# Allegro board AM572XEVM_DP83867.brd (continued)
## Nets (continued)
VOUT1_D12: P18.20 R136.2
VOUT1_D13: P18.15 R138.2
VOUT1_D14: P18.17 R139.2
VOUT1_D15: P18.14 R140.2
VOUT1_D16: P18.50 R141.2
VOUT1_D17: P18.51 R142.2
VOUT1_D18: P18.21 R143.2
VOUT1_D19: P18.22 R144.2
VOUT1_D20: P18.19 R145.2
VOUT1_D21: P18.23 R146.2
VOUT1_D22: P18.52 R147.2
VOUT1_D23: P18.24 R148.2
VOUT1_DE: P18.53 R150.2
VOUT1_HSYNC: P18.27 R152.2
VOUT1_RD0: R124.1 U11.F11(VOUT1_D0)
VOUT1_RD1: R125.1 U11.G10(VOUT1_D1)
VOUT1_RD2: R126.1 U11.F10(VOUT1_D2)
VOUT1_RD3: R127.1 U11.G11(VOUT1_D3)
VOUT1_RD4: R128.1 U11.E9(VOUT1_D4)
VOUT1_RD5: R129.1 U11.F9(VOUT1_D5)
VOUT1_RD6: R130.1 U11.F8(VOUT1_D6)
VOUT1_RD7: R131.1 U11.E7(VOUT1_D7)
VOUT1_RD8: R132.1 U11.E8(VOUT1_D8)
VOUT1_RD9: R133.1 U11.D9(VOUT1_D9)
VOUT1_RD10: R134.1 U11.D7(VOUT1_D10)
VOUT1_RD11: R135.1 U11.D8(VOUT1_D11)
VOUT1_RD12: R136.1 U11.A5(VOUT1_D12)
VOUT1_RD13: R138.1 U11.C6(VOUT1_D13)
VOUT1_RD14: R139.1 U11.C8(VOUT1_D14)
VOUT1_RD15: R140.1 U11.C7(VOUT1_D15)
VOUT1_RD16: R141.1 U11.B7(VOUT1_D16)
VOUT1_RD17: R142.1 U11.B8(VOUT1_D17)
VOUT1_RD18: R143.1 U11.A7(VOUT1_D18)
VOUT1_RD19: R144.1 U11.A8(VOUT1_D19)
VOUT1_RD20: R145.1 U11.C9(VOUT1_D20)
VOUT1_RD21: R146.1 U11.A9(VOUT1_D21)
VOUT1_RD22: R147.1 U11.B9(VOUT1_D22)
VOUT1_RD23: R148.1 U11.A10(VOUT1_D23)
VOUT1_RDCLK: R149.1 U11.D11(VOUT1_CLK)
VOUT1_RDE: R150.1 U11.B10(VOUT1_DE)
VOUT1_RHSYNC: R152.1 U11.C11(VOUT1_HSYNC)
VOUT1_RVSYNC: R153.1 U11.E11(VOUT1_VSYNC)
VOUT1_VSYNC: P18.28 R153.2
VTT: C296.1 C297.1 C298.1 C299.1 C313.1 C314.1 C328.1 C329.1 C330.1 C331.1 C332.1 C333.1 C342.1 C343.1 C351.1 C352.1 C353.1 C358.1 C362.1 C370.1 C371.1 C372.1 C379.1 C380.1 C395.1 C396.1 C397.1 C398.1 Q6.3(DRAIN) R279.2 R282.2 R289.1 R336.2 R337.2 R338.2 R339.2 R340.2 R341.2 R342.2 R343.2 R344.2 R345.2 R346.2 R347.2 R348.2 R349.2 R350.2 R351.2 R352.2 R353.2 R354.2 R355.2 R356.2 R357.2 R358.2 R359.2 R360.2 R361.2 R362.2 R363.2 R364.2 R365.2 R366.2 R367.2 R368.2 R369.2 R370.2 R371.2 R372.2 R373.2 R374.2 R375.2 R376.2 R377.2 R378.2 R379.2 R380.2 R381.2 R382.2 R383.2 U27.3(VO)
VTT_PGOOD: R286.2 U27.9(PGOOD)
VTT_REFOUT: C400.1 R289.2 U27.5(VOSNS)
VTT_TRAN: Q5.3(DRAIN) Q6.1(GATE) R335.2
VTT_VOSNS: C399.1 R290.1 R291.1 U27.6(REFOUT)
VUSB_3V3: C18.2 C236.1 C237.1 C238.1 U5.B9(LDOUSB_OUT) U11.AA12(VDDA33V_USB1) U11.Y12(VDDA33V_USB2)
WAKEUP1: R50.1 U11.AC17(WAKEUP1)
WAKEUP2: R51.1 U11.AB16(WAKEUP2)
ZQ1_HI: R275.1 U24.L8(ZQ)
ZQ1_LO: R276.1 U23.L8(ZQ)
ZQ2_HI: R278.1 U26.L8(ZQ)
ZQ2_LO: R277.1 U25.L8(ZQ)
N23410845: C98.2 U10.4(Y) U11.E23(RESETN)
N23730763: C197.1 C198.1 C199.1 C200.1 C203.1 L10.3 U11.M14(VDDA_ABE_PER) U11.N11(VDDA_DEBUG) U11.N12(VDDA_DSP) U11.N16(VDDA_MPU) U11.P14(VDDA_VIDEO) U11.P15(VDDA_GMAC_CORE) U11.P16(VDDA_DDR) U11.R14(VDDA_GPU) U11.R17(VDDA_IVA)
N24165486: C201.1 C202.1 C204.1 L11.1 U11.V13(VDDA_SATA) U11.W12(VDDA_USB3)
N26024435: C497.1 C498.1 C499.1 L24.1 U11.AA16(VDDA_PCIE1) U11.AA17(VDDA_PCIE0) U11.W14(VDDA_PCIE) U11.Y17(VDDA_HDMI)
N28155188: TP6.1 U11.K14(RSVD4)
N28613451: R318.2 R319.2 U5.E6(NRESWARM)
N28614009: R322.2 R323.2 R433.1 U5.E5(NSLEEP)
N28826254: R398.2 U33.9(PE1)
N28826261: R399.2 U33.8(PE2)
N29245750: R422.1 U11.AE14(RTC_OSC_XI_CLKIN32)
N29286052: R405.2 U9.3(B) U34.1(2A) U34.3(2Y)
N29286254: C476.1 U34.7(2Y)
N29286257: C476.2 R404.1 U34.5(2A) U34.6(2B)
N29321384: C495.1 R31.2 R409.1
N29512994: J3.2 R239.2
N29513031: J4.2 R182.2
N29513057: J6.2 R187.2
N29735394: R328.1 U17.41(PWRCTL_POL)
N29868563: Q7.1(G) R409.2 R410.1
N29882506: Q7.3(D) R408.2 U42.2(A)
N29907779: R413.1 R415.2 U42.4(Y)
N29975844: C496.1 U5.C1(OSC16MCAP)
N30391816: Q9.1(BASE) R423.2 R430.1 U43.2(CATHODE)
N30391875: R424.2 R425.1 R430.2 U43.1(REF)
N30606654: Q8.1(BASE) R418.2 R429.1 U35.2(CATHODE)
N30606697: R419.2 R420.1 R429.2 U35.1(REF)
N30851376: R478.2 U15.18(CLK_OUT)
N31260694: P5.28(LED1_C) R68.1
N31260700: P5.30(LED2_C) R69.2
N31260959: P5.34(LED4_C) R98.2
N31261983: P5.32(LED3_C) R97.1
N31304297: R477.2 U14.18(CLK_OUT)
N31316106: R479.2 U14.14(XO)
N31316228: R480.2 U15.14(XO)

Pads without a net: D20 2; D21 2; D22 2; D23 2 3; NOREF#12 1; NOREF#14 1; NOREF#18 1; NOREF#24 1; NOREF#25 1; NOREF#26 1; P4 6 17 18 19; P7 4; P8 4; P9 4; P10 2 3 6; P11 14; P18 9 58; P19 2 3 30 33; U5 B4 C9 C11 K4 K5 K10 L4 M11 N11; U7 8 13 15 23 24 25 26 27 28 29 30 31 32; U11 A27 AA1 AA2 AB1 AB2 AC1 AC2 AD3 AD8 AD9 AD14 AE3 AE5 AE6 AE8 AE9 AF4 AF6 AF8 AF9 AG2 B28 V23 V24 V25 V26 W19 W22 W23 Y5 Y9 Y10 Y25 Y26; U13 3; U14 13 20 21 22 23 39 40 46 48; U15 13 20 21 22 23 39 40 46 48; U16 3; U17 26 27 29 30 39 49 60; U18 10 11 12 13 15 19 20 22 23 28 30; U19 4; U21 14 15 16 17 19 20 21 22; U22 A1 A2 A6 A7 A8 A9 A10 A11 A12 A13 A14 B1 B7 B8 B9 B10 B11 B12 B13 B14 C1 C3 C5 C7 C8 C9 C10 C11 C12 C13 C14 D1 D2 D3 D4 D12 D13 D14 E1 E2 E3 E5 E8 E9 E10 E12 E13 E14 F1 F2 F3 F10 F12 F13 F14 G1 G2 G3 G10 G12 G13 G14 H1 H2 H3 H5 H12 H13 H14 J1 J2 J3 J5 J12 J13 J14 K1 K2 K3 K6 K7 K10 K12 K13 K14 L1 L2 L3 L12 L13 L14 M1 M2 M3 M7 M8 M9 M10 M11 M12 M13 M14 N1 N3 N6 N7 N8 N9 N10 N11 N12 N13 N14 P1 P2 P7 P8 P9 P10 P11 P12 P13 P14; U23 J1 J9 L1 L9; U24 J1 J9 L1 L9; U25 J1 J9 L1 L9; U26 J1 J9 L1 L9; U31 2 8; U33 7

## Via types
v1: diameter 0.457, hole 0.203, TOP to BOTTOM, 1408 vias
v2: diameter 0.406, hole 0.203, TOP to BOTTOM, 1193 vias
v3: diameter 0.356, hole 0.203, TOP to BOTTOM, 83 vias
v4: diameter 0.254, hole 0.152, TOP to BOTTOM, 7 vias
v5: diameter 0.635, hole 0.305, TOP to BOTTOM, 27 vias

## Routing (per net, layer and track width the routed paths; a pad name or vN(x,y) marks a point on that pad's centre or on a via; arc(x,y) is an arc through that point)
3V3_CDC: length 3.3
  TOP w0.254: U7.16 v1(25.94,49.05) ; U7.18 v1(27.96,47.5) ; U7.20 v1(28.96,47.5) ; U7.9 v1(25.91,52.55)
3V3_RC: length 2.4
  TOP w0.381: C11.2 v1(36.2,79.88)
  BOTTOM w0.381: v1(36.2,79.88) 36.16,79.92 R12.1
5V0: length 67.3
  TOP w0.254: U2.4 v1(42.43,71.24) ; v1(60.07,97.66) 60.07,97.41 60.33,97.16 60.81,97.16 61.07,96.9 U21.10
  TOP w0.381: R216.1 v1(69.22,3.68) ; v1(38.61,64.14) 37.97,63.5 R2.1 ; R218.1 v1(74.3,3.68) ; R215.1 v1(66.68,3.68) ; R217.1 v1(71.75,3.68)
  TOP w1.016: P3.4 R1.2
  SIG_L5 w0.381: 56.43,72.94 P3.4 ; P3.4 56.43,74.38 ; P3.4 57.87,74.38 ; P3.4 57.87,72.94
  PWR_L6 w0.381: P16.B2 119.15,56.65 ; P16.B2 117.47,57.83 ; P16.B2 115.8,56.65 ; P16.B2 117.47,55.47 ; 18.01,14.74 19.69,14.74 ; 19.69,14.74 19.69,15.92 ; 19.69,14.74 21.36,14.74 ; 19.69,14.74 19.69,13.56 ; 19.69,56.65 19.69,57.83 ; 19.69,56.65 18.01,56.65 ; 19.69,56.65 21.36,56.65 ; 19.69,56.65 19.69,55.47 ; 117.47,13.56 P18.B2 ; P18.B2 119.15,14.74 ; P18.B2 115.8,14.74 ; P18.B2 117.47,15.92
  SIG_L8 w0.381: v1(42.43,71.24) 42.43,71.64 43.56,72.77 56.26,72.77 P3.4
  BOTTOM w0.254: v2(71.79,69.61) 72.05,69.34 C17.2
  BOTTOM w0.381: v1(42.43,71.24) 40.37,71.24 38.61,69.47 v1(38.61,64.14) ; v1(60.07,97.66) 60.07,97.19 C264.1 ; R242.2 v1(61.34,102.87) ; R241.1 v1(60.33,102.87) ; C20.2 v1(74.17,73.41)
  vias: v1(60.33,103.76) v1(61.34,103.76)
5V0_COMP: length 3.6
  TOP w0.381: U1.6 36.07,64.77 36.23,64.93 C5.2 R4.1
5V0_RC: length 1.3
  TOP w0.381: R4.2 C6.1
5V0_SNS: length 3.7
  TOP w0.381: v1(36.2,64.14) 36.2,63.5 ; 36.2,63.5 U1.5 ; 36.2,63.5 R2.2
  BOTTOM w0.381: v1(36.2,64.14) R5.2
5V0_TAP: length 4
  TOP w0.381: P2.4 47.71,74.38 ; P2.4 46.27,74.38 ; P2.4 46.27,72.94 ; P2.4 47.71,72.94
  vias: v1(34.54,72.64) v1(35.31,72.64)
5V_FAN: length 9.5
  TOP w0.381: v1(116.46,49.53) 116.46,50.04 116.2,50.29 C49.1
  BOTTOM w0.381: J1.1 v1(116.46,49.53) 114.97,49.53 114.59,49.15 R396.1 114.17,48.77 113.67,48.26 U32.3
12V: length 21
  TOP w0.381: v1(24.45,90.16) 23.99,89.7 R240.1 ; U3.2 v1(25.02,79.88) ; U1.2 v1(27.43,66.04) ; U28.2 v1(98.68,43.81)
  PWR_L6 w0.381: 117.47,81.87 P16.B1 ; P16.B1 115.8,83.05 ; P16.B1 119.15,83.05 ; P16.B1 117.47,84.23
  BOTTOM w0.381: C445.1 110.11,44.32 ; 110.11,44.32 v1(111.51,44.32) ; 110.11,44.32 110.49,44.7 110.49,49.15 110.87,49.53 U32.2
  vias: v1(24.38,80.52) v1(24.38,79.25) v1(25.08,90.15) v1(25.68,90.16) v1(26.31,90.17) v1(26.8,66.67) v1(26.8,66.04) v1(97.92,44.45) v1(97.92,43.18)
GND: length 1608.7
  TOP w0.203: 93.98,47.62 93.98,47.22 U22.P4 ; v2(91.58,45.57) 91.83,45.07 91.83,45.06 ; 92.71,47.62 92.71,47.18 U22.P6 U22.N5 ; U22.N2 v4(95.07,46.81) ; v2(91.83,42.06) U22.E7 ; 93.33,43.57 93.82,43.57 v2(93.83,43.57) ; v2(93.32,42.06) U22.C4
  TOP w0.254: U11.U21 v2(62.59,43.21) U11.U20 ; U11.U21 v2(61.79,42.41) U11.T21 v2(61.79,41.61) U11.R21 ; U11.U21 v2(61.79,43.21) ; U23.M1 v2(38.58,60.01) 38.5,60.1 C284.2 R51.2 ; C518.2 v1(91.52,73.33) ; D21.4 70.98,12.99 v1(70.94,12.95) ; U11.A14 v2(68.19,29.61) ; v2(35.38,19.2) U25.T9 ; v2(40.98,53.61) U23.J8 ; C363.2 36.89,26.49 v2(36.98,26.4) U25.P1 ; U5.B10 v2(70.99,69.61) 70.59,69.21 U5.B11 ; C551.2 v1(105.26,73.63) ; U5.E4 v2(68.59,75.21) U5.D4 ; U5.E4 67.79,75.21 v2(67.79,75.21) U5.F4 ; U5.E4 v2(67.79,74.41) ; C510.2 85.93,64.77 v1(85.8,64.64) ; U11.AA14 v2(68.19,46.41) U11.AB14 ; C376.2 36.89,19.11 v2(36.98,19.2) U25.P9 ; U11.AD1 v2(78.59,48.81) ; v2(68.59,72.01) U5.E7 67.79,72.01 v2(67.79,72.01) ; v2(68.59,72.01) 68.59,72.01 U5.D7 v2(69.39,72.01) ; v2(68.59,72.01) U5.E8 ; v2(47.38,60.01) U23.B1 ; C398.2 31.27,21.46 U27.4 29.34,21.46 v5(29.08,21.72) ; v2(44.98,42.41) U24.E8 ; U31.12 79.12,76.33 ; 79.12,76.33 79.12,77.09 79.36,77.33 U31.14 ; 79.12,76.33 79.12,75.82 79.59,75.35 U31.10 v1(80.14,74.99) ; v2(58.59,44.81) U11.W25 v2(59.39,44.81) U11.W24 ; U5.B2 v2(70.19,76.01) ; U5.B2 v2(70.99,76.81) U5.A1 ; U5.B2 70.19,76.81 70.19,76.81 U5.C2 69.79,76.41 v2(70.19,76.01) ; v2(70.19,76.01) U5.C3 v2(69.39,75.21) U5.D4 ; v2(65.39,74.41) U5.H5 v2(65.39,73.61) ; v2(65.39,74.41) U5.H4 v2(65.39,75.21) ; v2(65.39,74.41) U5.J4 v2(64.59,75.21) U5.K3 v2(63.79,76.01) ; v2(68.99,37.61) U11.L13 v2(68.19,37.61) U11.L14 ; v2(70.59,46.41) U11.AA10 v2(71.39,46.41) U11.AA9 v2(72.19,46.41) U11.AA8 v2(72.99,46.41) ; v2(70.59,46.41) U11.AA11 ; v2(70.59,46.41) U11.AB11 v2(70.59,47.21) ; v1(62.56,13.23) 62.57,13.22 D23.4 ; v2(66.59,44.81) U11.W15 v2(66.59,44.01) U11.V15 v2(66.59,43.21) U11.U15 v2(66.59,42.41) U11.T15 v2(66.59,41.61) U11.R15 ; v1(74.17,75.31) 74.49,74.99 U31.1 ; v5(78.74,84.84) U33.3 ; v5(78.74,84.84) U33.18 ; v5(78.74,84.84) U33.13 v1(78.74,87.42) ; v2(69.79,41.61) U11.T11 ; v2(69.79,41.61) U11.R12 v2(68.99,41.61) ; v2(69.79,41.61) U11.T12 ; U11.T11 v2(69.79,42.41) U11.T12 ; U11.T11 v2(70.59,42.41) U11.T10 v2(71.39,42.41) ; U5.D6 v2(69.39,73.61) U5.D5 v2(69.39,74.41) U5.D4 ; U11.N25 v2(59.39,39.21) U11.N24 ; U11.T12 v2(68.99,41.61) ; v2(35.38,37.6) U26.T1 ; v1(56.01,11.75) 55.56,11.75 55.25,12.06 C260.2 ; C318.1 36.89,41.52 v2(36.98,41.61) U24.P9 ; U11.J28 v2(56.19,36.01) ; D12.2 v1(50.16,95.5) ; v2(44.18,19.2) U25.F9 ; D14.2 v1(52.7,95.5) ; v1(69.22,17.02) 69.34,17.14 69.34,18.03 69.72,18.41 U4.2 ; U7.22 29.96,49.26 30.23,49.53 v1(30.48,49.53) ; v1(58.04,100.58) P11.11 ; C547.2 110.88,66.84 v1(111.05,67.01) ; U11.A2 v2(77.79,29.61) U11.A1 ; 99.51,63.71 99.51,63.54 v1(99.38,63.41) ; U11.B1 v2(78.59,30.41) U11.A1 ; v1(28.45,49.53) 27.93,50.05 U7.14 ; C556.2 v1(103.76,73.61) ; v2(44.18,30.4) U26.F9 ; U5.N1 v2(61.39,76.81) U5.N2 v2(62.19,76.81) ; U5.N1 v2(62.19,76.81) ; U5.N1 v2(62.19,77.61) U5.M1 v2(62.19,76.81) ; v2(43.38,53.61) U23.G8 ; U24.M1 v2(38.58,48.81) 38.5,48.89 C307.2 ; U11.A23 v2(60.19,29.61) ; U23.P9 v2(36.98,52.81) 36.89,52.72 C292.2 ; v2(45.78,31.2) U26.D8 ; U11.AA15 v2(66.59,46.41) ; v2(72.99,51.21) U11.AH8 ; C336.2 38.5,37.69 v2(38.58,37.6) U26.M1 ; P11.2 v1(53.54,100.58) ; v2(65.39,73.61) 65.39,73.61 U5.J6 ; v2(65.39,73.61) U5.H6 v2(65.39,72.81) ; v2(62.59,47.21) U11.AB20 v2(62.59,46.41) U11.AA20 ; v1(61.72,18.41) 61.61,18.53 U18.6 ; C306.2 36.89,48.89 v2(36.98,48.81) U24.P1 ; D19.2 v1(59.05,95.5) ; v5(77.99,84.09) 77.74,84.34 U33.19 ; v2(44.98,60.01) U23.E1 ; v2(44.98,48.81) U24.E1 ; D13.2 v1(51.44,95.5) ; C511.2 89.54,60.12 v1(89.53,60.12) ; v2(63.39,38.41) U11.M19 v2(63.39,39.21) U11.N19 ; C522.2 85.91,63.25 v1(85.78,63.12) ; v2(72.99,34.41) U11.G8 v2(72.19,34.41) U11.G9 ; v2(72.99,34.41) U11.G7 v2(73.79,34.41) U11.F7 ; v2(72.99,34.41) U11.F7 ; U23.P1 v2(36.98,60.01) 36.89,60.1 C283.2 ; v2(47.38,48.81) U24.B1 ; v2(68.59,70.41) U5.D10 ; v2(68.59,70.41) U5.E10 ; v2(68.59,70.41) U5.E9 68.19,70.81 v2(67.79,70.41) ; U5.D10 68.99,70.01 v2(68.59,69.61) U5.E10 ; U5.D10 v2(69.39,69.61) ; v2(40.98,36.8) U26.J2 ; v2(61.39,67.21) U5.N13 v2(62.19,68.01) ; U27.8 v5(28.58,20.95) ; v2(47.38,41.61) U24.B9 ; U11.AD10 v2(71.39,48.81) U11.AE10 ; Q4.4 76.21,5.52 76.39,5.7 R222.2 ; v2(64.99,44.01) U11.V17 v2(64.99,43.21) U11.U17 v2(64.99,42.41) ; v2(40.98,48.01) U24.J2 ; v2(47.38,24.8) U25.B3 ; U11.A1 v2(78.59,29.61) ; C555.2 v1(106.76,73.63) ; D17.2 v1(56.52,95.5) ; v2(35.38,30.4) U26.T9 ; v2(66.99,74.41) U5.F4 ; v2(66.99,74.41) 67.39,74.01 U5.F5 ; v2(66.99,74.41) U5.G4 v2(66.99,75.21) U5.F4 ; v2(66.99,74.41) U5.G5 ; U5.F4 v2(67.79,74.41) ; U5.C12 v2(70.19,68.01) ; U26.P9 v2(36.98,30.4) 36.89,30.32 C347.2 ; D33.3 v1(98.42,21.46) ; v5(77.99,85.59) 77.74,85.34 U33.17 ; v2(43.38,41.61) U24.G9 ; D16.2 v1(55.25,95.5) ; D38.3 v1(106.5,21.46) ; C512.2 97.34,63.92 v1(97.5,63.76) ; v2(48.18,52.81) U23.A9 ; U11.AH20 v2(62.59,51.21) ; C364.2 38.5,26.49 v2(38.58,26.4) U25.M1 ; v2(35.38,60.01) U23.T1 ; D31.3 v1(100.51,21.46) ; U26.P1 v2(36.98,37.6) 36.89,37.69 C335.2 ; v2(40.98,25.6) U25.J2 ; v2(40.98,42.41) U24.J8 ; v2(43.38,52.81) U23.G9 ; v2(47.38,26.4) U25.B1 ; U5.A13 v2(70.99,68.01) ; v2(62.19,76.81) U5.M2 ; 74.06,7.36 v1(74.14,7.36) 74.15,7.34 Q4.1 ; v2(67.79,74.41) U5.F5 ; U5.F5 v2(67.79,73.61) U5.F6 ; v1(85.09,27.81) 84.84,27.81 84.58,27.56 84.58,26.67 ; U11.A6 v2(74.59,29.61) ; U31.27 74.29,76.33 74.17,76.45 v1(74.17,77.34) 74.18,77.33 U31.25 ; v2(43.38,19.2) U25.G9 ; v2(35.38,26.4) U25.T1 ; 62.87,95.5 v1(62.36,95.5) ; 62.87,95.5 63.06,95.3 63.06,94.53 ; 62.87,95.5 63.06,95.7 63.06,96.48 ; Q3.4 66.08,5.12 66.25,5.29 R220.2 v1(66.68,4.65) ; v2(67.79,70.41) U5.F10 v2(67.79,69.61) 67.79,69.61 U5.E10 ; v2(67.79,70.41) U5.E10 ; v2(67.79,70.41) U5.F9 ; U2.5 42.43,68.97 v5(42.67,69.22) ; U5.L8 v2(62.99,71.21) U5.L9 v2(62.99,70.41) U5.L10 v2(62.99,69.61) ; v1(99.38,64.91) 99.51,65.04 99.51,65.2 ; v2(44.98,31.2) U26.E8 ; U5.J10 v2(64.59,70.41) U5.J9 ; U5.J10 v2(64.59,69.61) ; U5.J10 65.39,69.61 v2(65.39,69.61) U5.H10 65.79,70.01 v2(66.19,69.61) U5.G10 ; v2(47.38,37.6) U26.B1 ; v2(44.98,59.21) U23.E2 ; v2(44.98,20) U25.E8 ; U11.K1 v2(78.59,36.81) ; v2(68.59,71.21) U5.E8 ; U5.E8 68.19,71.61 v2(67.79,72.01) ; v2(44.98,25.6) U25.E2 ; U20.4 v1(27.32,36.08) ; v2(43.38,48.81) U24.G1 ; U11.F7 v2(73.79,33.61) ; v2(67.79,72.01) U5.F7 v2(66.99,72.01) U5.G7 ; U24.M9 v2(38.58,41.61) 38.5,41.52 C319.2 ; v1(97.51,65.76) 97.34,65.59 C519.2 ; U11.AH28 v2(56.19,52.01) ; v2(47.38,36) U26.B3 ; U11.A28 v2(56.19,29.61) ; v2(35.38,52.81) U23.T9 ; U23.M9 v2(38.58,52.81) 38.5,52.72 C293.2 ; 77.09,78.17 77.09,78.86 v1(76.96,78.99) ; v2(47.38,58.41) U23.B3 ; U11.U14 v2(68.19,42.41) U11.T14 ; U11.E19 v2(63.39,32.81) U11.D19 v2(63.39,32.01) ; C377.2 38.5,19.11 v2(38.58,19.2) U25.M9 ; v1(27.3,37.85) 27.57,37.58 U20.1 ; v2(43.38,42.41) U24.G8 ; 79.5,41.66 78.64,41.66 U11.R1 ; U11.W1 v2(78.59,44.81) ; v2(68.99,41.61) U11.R13 ; U22.H10 91.06,44.06 91.31,43.81 v2(91.31,43.05) ; D22.4 v1(76.14,9.03) ; v2(43.38,26.4) U25.G1 ; v2(45.78,37.6) U26.D1 ; v1(83.69,85.95) U6.4 ; U5.J6 v2(64.59,73.61) ; U5.J6 v2(65.39,72.81) ; U5.M12 v2(62.19,68.01) ; v2(62.19,68.01) U5.M13 ; v2(43.38,60.01) U23.G1 ; U11.K25 v2(59.39,36.81) U11.K24 ; v2(64.19,42.41) U11.T18 v2(64.99,42.41) ; v2(45.78,42.41) U24.D8 ; U11.AD13 v2(68.99,48.81) U11.AE13 ; v1(55.04,100.58) P11.5 ; v2(45.78,26.4) U25.D1 ; D20.4 v1(67.12,9.03) ; C526.2 v1(90.02,73.33) ; v2(44.18,41.61) U24.F9 ; C400.2 v1(28.58,23.24) ; v1(60.07,94.74) 60.28,94.53 U21.13 ; v2(47.38,47.21) U24.B3 ; D18.2 v1(57.79,95.5) ; P11.8 v1(56.54,100.56) ; v2(45.78,20) U25.D8 ; U11.E13 v2(68.99,32.81) U11.D13 v2(68.99,32.01) ; U11.AG1 v2(78.59,51.21) U11.AH1 ; v2(47.38,30.4) U26.B9 ; v1(111.02,65) 110.88,65.14 C561.2 ; v1(55.12,17.02) 55.12,17.27 55.38,17.53 U18.21 ; v2(71.79,72.01) U5.A7 ; v2(40.98,59.21) U23.J2 ; v2(35.38,48.81) U24.T1 ; C527.2 v1(93.01,73.33) ; v2(47.38,52.81) U23.B9 ; v2(43.38,20) U25.G8 ; D15.2 v1(53.98,95.5) ; v2(45.78,53.61) U23.D8 ; v2(62.99,74.41) U5.L5 v2(62.99,73.61) U5.L6 v2(62.99,72.81) U5.L7 ; v2(44.98,37.6) U26.E1 ; v2(44.18,52.81) U23.F9 ; v2(43.38,31.2) U26.G8 ; v2(44.98,26.4) U25.E1 ; U11.AH1 v2(78.59,52.01) ; U11.AH1 v2(77.79,52.01) U11.AH2 ; v2(69.79,35.21) U11.H12 v2(69.79,36.01) U11.J12 ; U11.W28 v2(56.19,44.81) ; v2(65.39,72.81) U5.H7 ; v2(76.19,36.81) U11.K4 v2(75.39,36.81) U11.K5 ; v2(43.38,30.4) U26.G9 ; D27.3 v1(84.45,18.29) ; v2(44.98,53.61) U23.E8 ; v2(40.98,20) U25.J8 ; v2(35.38,41.61) U24.T9 ; v2(43.38,37.6) U26.G1 ; U11.N15 v2(66.59,39.21) ; v1(90.81,60.55) 90.82,60.57 C520.2 ; v1(60.71,97.66) 60.71,97.71 61.04,98.05 P11.17 ; C562.2 v1(103.36,60.42) ; v2(40.98,31.2) U26.J8 ; U11.T17 v2(64.99,42.41) ; U11.AE19 v2(63.39,48.81) U11.AD19 ; v1(64.01,7.01) 64.02,7 Q3.1 ; U11.N14 v2(68.19,39.21) ; v2(47.38,19.2) U25.B9 ; D25.3 v1(89.36,18.29) ; C348.2 38.5,29.25 v1(38.6,29.35) 38.58,29.36 v2(38.58,30.4) U26.M9 ; v2(44.98,48.01) U24.E2 ; v2(66.59,36.01) U11.J15 v2(66.59,36.81) U11.K15 ; v2(45.78,60.01) U23.D1 ; D26.3 v1(86.36,18.29) ; v2(70.99,71.21) U5.B8 ; U11.AD24 v2(59.39,48.81) ; C549.2 v1(104.58,60.85) ; U11.F1 v2(78.59,33.61) ; U11.P28 v2(56.19,40.01) ; v2(44.98,36.8) U26.E2 ; v2(45.78,48.81) U24.D1 ; v2(48.18,19.2) U25.A9 ; v2(48.18,30.4) U26.A9 ; v2(71.79,75.21) U5.A4 ; v2(48.18,41.61) U24.A9
  TOP w0.381: P5.20 94.94,84.46 ; P5.20 94.94,85.72 ; P5.20 93.68,85.72 ; J4.3 116.08,95.71 ; J4.3 116.08,93.83 ; J4.3 117.02,94.77 ; J4.3 115.14,94.77 ; 34.42,101.62 P1.SHLD4 ; P1.SHLD4 36.23,101.62 ; P1.SHLD4 34.42,98.62 ; P1.SHLD4 36.23,98.62 ; 85.6,65.26 C510.2 85.93,65.59 ; R232.2 v1(64.01,17.53) ; Q6.2 31.24,16.79 ; Q6.2 31.9,16.21 ; Q6.2 v1(31.24,15.37) ; v1(86.11,79.88) C30.2 ; R440.1 v1(88.39,73.3) ; R440.1 87.96,73.12 ; R440.1 87.96,72.74 ; 117.51,62.56 R432.2 ; R432.2 117.51,63.42 ; R432.2 116.97,62.99 v1(116.84,63.12) ; 113.25,86.17 P16.A2 ; P16.A2 114.92,87.35 ; P16.A2 116.6,86.17 ; P16.A2 114.92,85 ; v1(110.26,53.52) 109.97,53.81 U44.3 ; P1.SHLD1 48.13,96.42 ; P1.SHLD1 48.13,93.42 ; P1.SHLD1 46.32,93.42 ; P1.SHLD1 46.32,96.42 ; P10.1 26.97,45.72 ; P10.1 26.04,46.66 ; P10.1 25.1,45.72 ; P10.1 26.04,44.78 ; R183.2 v1(122.3,69.6) ; C442.2 75.31,69.33 ; C442.2 74.73,68.71 ; C442.2 75.56,68.96 76.07,68.96 ; C442.2 75.9,68.71 ; C442.2 75.56,68.45 76.33,68.45 v1(76.45,68.33) 76.45,68.96 ; v1(103.76,73.61) U50.8 U50.3 ; C410.2 v1(111.51,42.71) ; 78.56,16.84 MH5.1 ; MH5.1 78.56,20.25 ; MH5.1 81.97,20.25 ; U19.2 56.39,12.7 56.01,12.32 v1(56.01,11.75) U19.3 ; 97.67,64.39 C512.2 97.34,64.72 ; 102.16,73.42 R441.1 101.73,73.02 ; 73.97,97.48 P6.4 ; P6.4 74.85,98.35 ; P6.4 73.09,98.35 ; P6.4 73.97,99.23 ; 90.04,81.92 90.76,82.63 ; 90.04,81.92 89.33,82.63 ; 90.04,81.92 90.76,81.2 ; 90.04,81.92 89.33,81.2 ; 105.72,96.13 P5.1 ; P5.1 105.72,94.88 ; P5.1 106.98,94.88 ; P1.2 42.88,95.17 ; P1.2 39.67,95.17 ; P1.2 42.88,96.97 ; P1.2 39.67,96.97 ; 85.58,63.74 C522.2 85.91,64.07 ; 89.53,29.84 v1(92.71,29.84) ; v1(92.71,29.84) 95.89,29.84 ; v1(92.71,29.84) 92.71,26.67 ; v1(92.71,29.84) 92.71,33.02 ; v1(93.01,73.33) U47.8 U47.3 ; 86.36,14.11 P13.7 ; P13.7 87.17,14.92 ; P13.7 85.55,14.92 ; C295.2 46.23,60.45 v2(45.78,60.01) ; 41.96,66.17 D3.1 ; D3.1 42.55,67.18 v1(42.42,67.31) ; D3.1 43.13,66.17 ; 114.92,43.09 P18.A2 ; P18.A2 113.25,44.26 ; P18.A2 116.6,44.26 ; P18.A2 114.92,45.44 ; v5(101.73,28.7) 101.73,29.56 R293.1 ; v1(122.3,60.45) R190.2 R191.2 ; C433.2 v1(30.99,56.39) ; 99.18,65.53 C560.2 ; C560.2 99.51,65.2 ; C560.2 99.51,65.86 ; R188.2 R192.2 v1(122.3,64.52) ; U44.3 110.35,54.47 ; U44.3 109.97,55.16 ; 15.46,44.26 17.14,44.26 ; 17.14,44.26 18.81,44.26 ; 17.14,44.26 17.14,45.44 ; 17.14,44.26 17.14,43.09 ; 110.88,65.99 C561.2 111.21,65.66 ; P13.4 90.67,13.43 ; P13.4 89.86,12.61 ; P13.4 89.05,13.43 ; 17.14,85 17.14,86.17 ; 17.14,86.17 18.81,86.17 ; 17.14,86.17 17.14,87.35 ; 17.14,86.17 15.46,86.17 ; 77.44,85.19 U33.17 77.44,85.04 ; J6.1 111.94,92.23 ; J6.1 110.06,92.23 ; J6.1 111,93.17 ; J6.1 111,91.29 ; 111.21,66.4 C547.2 110.88,66.07 ; 60.74,53.17 R244.2 ; R244.2 60.71,53.63 v1(60.71,54.74) ; R244.2 60.74,54.02 ; R244.2 60.34,53.59 ; v1(90.02,73.33) U48.8 U48.3 ; 31.46,104.38 S1.1 ; S1.1 30.52,105.32 ; S1.1 32.4,105.32 ; 80,83.58 v5(78.74,84.84) 77.48,84.21 ; 76.45,68.96 v1(76.45,69.34) 76.07,68.96 ; 76.45,68.96 76.07,68.96 ; C49.2 v1(116.46,47.5) ; C49.2 115.06,46.62 ; C49.2 114.06,47.5 ; 69.94,53.17 R395.2 ; R395.2 69.94,54.02 ; R395.2 70.35,53.59 ; P6.11 81.97,96.45 ; P6.11 81.28,95.7 ; P6.11 81.28,97.2 ; C15.2 R66.2 v1(65.41,17.02) ; R287.1 v1(28.58,17.65) ; 119.38,47.6 J1.2 ; J1.2 118.69,48.29 ; J1.2 120.07,48.29 ; P15.16 104.32,18.13 ; P15.16 103.5,17.31 ; P15.16 103.5,18.94 ; P15.16 102.69,18.13 ; 46.32,98.62 P1.SHLD3 ; P1.SHLD3 46.32,101.62 ; P1.SHLD3 48.13,101.62 ; P1.SHLD3 48.13,98.62 ; C585.2 84.73,64.88 ; C585.2 v1(84.35,65.12) ; C585.2 84.75,64.46 ; v5(101.73,33.78) 101.73,34.64 R298.2 ; 56.43,69.3 P3.6 56.43,67.86 ; R221.2 v1(73,5.03) ; 88.69,36.68 R329.1 ; R329.1 v1(88.9,37.08) ; R329.1 89.11,36.68 ; 106.19,16.63 107.01,16.63 ; 107.01,16.63 107.01,15.81 ; 107.01,16.63 107.82,16.63 ; 53.04,2.25 S2.1 ; S2.1 53.98,3.19 ; S2.1 54.91,2.25 ; 72.97,96.45 P6.5 ; P6.5 73.66,95.7 ; P6.5 73.66,97.2 ; v1(49.56,68.61) 49.56,69.37 49.82,69.64 51.19,69.64 51.46,69.37 U13.2 ; 90.98,60.24 C520.2 91.31,60.24 ; U51.3 85.07,61.46 ; U51.3 84.69,62.14 ; U51.3 84.69,60.57 v1(84.71,60.55) ; v1(112.67,64.77) 112.93,64.52 R181.2 R180.2 R193.2 R194.2 R195.2 113.03,60.45 v1(112.65,60.07) ; P2.6 47.71,67.86 ; P2.6 46.27,67.86 ; P2.6 46.27,69.3 ; P2.6 47.71,69.3 ; R206.1 85.22,26.04 84.58,26.67 ; v1(32.89,20.45) C391.2 C392.2 ; 22.28,93.47 D41.1 ; D41.1 23.43,94.09 ; D41.1 v1(22.86,94.72) ; v1(93.98,48.13) 93.98,47.62 ; L12.2 v1(58.42,21.08) ; 99.51,63.71 C550.2 ; C550.2 99.51,64.36 ; C550.2 99.18,64.03 ; L21.2 v1(83.31,75.82) ; v1(82.3,41.66) 79.5,41.66 ; U4.4 68.67,20.11 v1(67.9,20.87) ; 77.44,84.63 U33.19 77.44,84.48 ; v1(25.78,16.38) 25.92,16.52 Q5.2 ; 115.14,97.31 J3.3 ; J3.3 116.08,98.25 ; J3.3 116.08,96.37 ; J3.3 117.02,97.31 ; 66.71,4.65 v1(66.68,4.65) ; 106.19,13.43 107.01,13.43 ; 107.01,13.43 107.82,13.43 ; 107.01,13.43 107.01,12.61 ; 105.38,60.85 C549.2 105.05,60.52 ; v1(29.72,42.8) C436.2 C437.2 ; 97.34,64.82 C519.2 97.67,65.15 ; 26.53,16.16 Q5.2 ; Q5.2 26.53,16.87 ; Q5.2 26.96,16.52 ; C272.1 69.17,5.66 68.94,5.89 C271.2 v1(68.94,7.16) ; v1(106.76,73.63) U49.8 U49.3 ; R231.2 v1(64.01,16.26) ; 77.44,85.13 U33.18 77.44,84.54 ; v1(74.17,70.36) C50.2 v1(76.45,70.36) ; C32.2 C31.2 v1(83.69,88.99) ; v1(39.37,64.14) C6.2 ; 104.16,60.42 C562.2 103.84,60.09 ; 36.23,96.42 P1.SHLD2 34.42,96.42 ; U12.2 v1(56.01,8.89) ; C501.2 110.05,57.45 ; C501.2 v1(109.64,58.1) ; C501.2 110.03,57.88 ; 77.47,95.7 P6.8 77.47,97.2 ; 92.71,47.62 v1(92.71,48.13) ; R222.2 v1(76.81,5.03) ; C252.2 v1(64.01,22.61) ; 90.43,60.12 C511.2 90.43,60.28 ; R219.2 v1(62.87,4.62) ; C390.2 v1(28.58,18.54) ; C104.2 v1(61.59,11.3) C261.2 ; R311.2 v1(24.89,47.5) ; R54.1 v1(60.83,7.4) ; C399.2 v1(24.38,22.23) ; R312.2 v1(25.91,56.39)
  GND_L2 w0.381: 34.42,98.62 P1.SHLD4 ; P1.SHLD4 34.42,101.62 ; P1.SHLD4 36.23,98.62 ; P1.SHLD4 36.23,101.62 ; 53.04,2.25 S2.1 ; S2.1 53.98,3.19 ; S2.1 54.91,2.25 ; 46.27,67.86 P2.6 ; P2.6 47.71,67.86 ; P2.6 46.27,69.3 ; P2.6 47.71,69.3 ; J6.1 111,93.17 ; J6.1 111.94,92.23 ; J6.1 110.06,92.23 ; J6.1 111,91.29 ; 25.1,45.72 P10.1 ; P10.1 26.04,46.66 ; P10.1 26.04,44.78 ; P10.1 26.97,45.72 ; P1.SHLD1 48.13,93.42 ; P1.SHLD1 46.32,96.42 ; P1.SHLD1 48.13,96.42 ; P1.SHLD1 46.32,93.42 ; 73.09,98.35 P6.4 ; P6.4 73.97,97.48 ; P6.4 74.85,98.35 ; P6.4 73.97,99.23 ; P15.16 104.32,18.13 ; P15.16 103.5,18.94 ; P15.16 102.69,18.13 ; 77.47,97.2 P6.8 77.47,95.7 ; 46.32,98.62 P1.SHLD3 ; P1.SHLD3 46.32,101.62 ; P1.SHLD3 48.13,101.62 ; P1.SHLD3 48.13,98.62 ; S1.1 32.4,105.32 ; S1.1 31.46,104.38 ; S1.1 30.52,105.32 ; 17.14,43.09 17.14,44.26 ; 17.14,44.26 17.14,45.44 ; 17.14,44.26 15.46,44.26 ; 17.14,44.26 18.81,44.26 ; 115.14,94.77 J4.3 ; J4.3 117.02,94.77 ; J4.3 116.08,93.83 ; J4.3 116.08,95.71 ; 90.04,81.92 90.76,81.2 ; 90.04,81.92 89.33,82.63 ; 90.04,81.92 89.33,81.2 ; 90.04,81.92 90.76,82.63 ; P13.7 86.36,15.74 ; P13.7 85.55,14.92 ; P13.7 87.17,14.92 ; J3.3 116.08,98.25 ; J3.3 117.02,97.31 ; J3.3 116.08,96.37 ; J3.3 115.14,97.31 ; P13.4 90.67,13.43 ; P13.4 89.05,13.43 ; P13.4 89.86,12.61 ; 107.01,13.43 107.82,13.43 ; 107.01,13.43 107.01,12.61 ; 107.01,13.43 106.19,13.43 ; J1.2 120.07,48.29 ; J1.2 119.38,47.6 ; J1.2 118.69,48.29 ; P16.A2 114.92,87.35 ; P16.A2 116.6,86.17 ; P16.A2 113.25,86.17 ; P16.A2 114.92,85 ; 114.92,43.09 P18.A2 ; P18.A2 116.6,44.26 ; P18.A2 113.25,44.26 ; P18.A2 114.92,45.44 ; 93.68,85.72 P5.20 ; P5.20 94.94,85.72 ; P5.20 93.68,84.46 ; P5.20 94.94,84.46 ; 39.67,96.97 P1.2 ; P1.2 42.88,95.17 ; P1.2 39.67,95.17 ; P1.2 42.88,96.97 ; P1.SHLD2 36.23,93.42 ; P1.SHLD2 36.23,96.42 ; P1.SHLD2 34.42,93.42 ; P1.SHLD2 34.42,96.42 ; 107.01,15.81 107.01,16.63 ; 107.01,16.63 106.19,16.63 ; 107.01,16.63 107.82,16.63 ; 72.97,96.45 P6.5 ; P6.5 73.66,95.7 ; P6.5 73.66,97.2 ; P6.11 81.97,96.45 ; P6.11 81.28,97.2 ; P6.11 81.28,95.7 ; MH5.1 81.97,20.25 ; MH5.1 78.56,16.84 ; MH5.1 81.97,16.84 ; MH5.1 78.56,20.25 ; 17.14,86.17 17.14,87.35 ; 17.14,86.17 17.14,85 ; 17.14,86.17 18.81,86.17 ; 17.14,86.17 15.46,86.17 ; 105.72,96.13 P5.1 ; P5.1 105.72,94.88 ; P5.1 106.98,96.13 ; P5.1 106.98,94.88 ; 56.43,67.86 P3.6 ; P3.6 56.43,69.3 ; P3.6 57.87,69.3 ; P3.6 57.87,67.86 ; 102.88,14.3 P15.7 ; P15.7 104.13,14.3 ; P15.7 102.88,15.55 ; P15.7 104.13,15.55
  GND_L4 w0.381: J1.2 120.07,48.29 ; J1.2 118.69,48.29 ; J1.2 119.38,47.6 ; J3.3 116.08,98.25 ; J3.3 116.08,96.37 ; J3.3 117.02,97.31 ; J3.3 115.14,97.31 ; P1.SHLD3 48.13,101.62 ; P1.SHLD3 48.13,98.62 ; P1.SHLD3 46.32,101.62 ; P1.SHLD3 46.32,98.62 ; 25.1,45.72 P10.1 ; P10.1 26.04,44.78 ; P10.1 26.04,46.66 ; P10.1 26.97,45.72 ; J4.3 116.08,95.71 ; J4.3 117.02,94.77 ; J4.3 116.08,93.83 ; J4.3 115.14,94.77 ; MH5.1 81.97,16.84 ; MH5.1 81.97,20.25 ; MH5.1 78.56,16.84 ; MH5.1 78.56,20.25 ; P1.SHLD4 36.23,101.62 ; P1.SHLD4 36.23,98.62 ; P1.SHLD4 34.42,101.62 ; P1.SHLD4 34.42,98.62 ; P6.11 81.97,96.45 ; P6.11 81.28,95.7 ; P6.11 81.28,97.2 ; 110.06,92.23 J6.1 ; J6.1 111,93.17 ; J6.1 111,91.29 ; J6.1 111.94,92.23 ; 102.88,15.55 P15.7 ; P15.7 104.13,15.55 ; P15.7 104.13,14.3 ; P15.7 102.88,14.3 ; P13.7 87.17,14.92 ; P13.7 85.55,14.92 ; P13.7 86.36,15.74 ; 15.46,86.17 17.14,86.17 ; 17.14,86.17 17.14,85 ; 17.14,86.17 17.14,87.35 ; 17.14,86.17 18.81,86.17 ; P6.5 73.66,97.2 ; P6.5 73.66,95.7 ; P6.5 72.97,96.45 ; 56.43,69.3 P3.6 ; P3.6 57.87,67.86 ; P3.6 56.43,67.86 ; P3.6 57.87,69.3 ; P1.SHLD1 48.13,96.42 ; P1.SHLD1 46.32,93.42 ; P1.SHLD1 48.13,93.42 ; P1.SHLD1 46.32,96.42 ; P15.16 103.5,18.94 ; P15.16 102.69,18.13 ; P15.16 104.32,18.13 ; 113.25,44.26 P18.A2 ; P18.A2 116.6,44.26 ; P18.A2 114.92,45.44 ; P18.A2 114.92,43.09 ; P16.A2 116.6,86.17 ; P16.A2 113.25,86.17 ; P16.A2 114.92,85 ; P16.A2 114.92,87.35 ; 89.33,82.63 90.04,81.92 ; 90.04,81.92 90.76,81.2 ; 90.04,81.92 90.76,82.63 ; 90.04,81.92 89.33,81.2 ; 15.46,44.26 17.14,44.26 ; 17.14,44.26 18.81,44.26 ; 17.14,44.26 17.14,45.44 ; 17.14,44.26 17.14,43.09 ; S2.1 53.98,3.19 ; S2.1 54.91,2.25 ; S2.1 53.04,2.25 ; P13.4 90.67,13.43 ; P13.4 89.05,13.43 ; P13.4 89.86,12.61 ; 77.47,95.7 P6.8 77.47,97.2 ; 46.27,69.3 P2.6 ; P2.6 47.71,67.86 ; P2.6 46.27,67.86 ; P2.6 47.71,69.3 ; 106.19,16.63 107.01,16.63 ; 107.01,16.63 107.82,16.63 ; 107.01,16.63 107.01,15.81 ; P6.4 73.97,99.23 ; P6.4 73.97,97.48 ; P6.4 73.09,98.35 ; P6.4 74.85,98.35 ; 34.42,96.42 P1.SHLD2 ; P1.SHLD2 34.42,93.42 ; P1.SHLD2 36.23,96.42 ; P1.SHLD2 36.23,93.42 ; 39.67,95.17 P1.2 ; P1.2 42.88,96.97 ; P1.2 42.88,95.17 ; P1.2 39.67,96.97 ; 106.19,13.43 107.01,13.43 ; 107.01,13.43 107.01,12.61 ; 107.01,13.43 107.82,13.43 ; 30.52,105.32 S1.1 ; S1.1 32.4,105.32 ; S1.1 31.46,104.38 ; P5.20 94.94,85.72 ; P5.20 94.94,84.46 ; P5.20 93.68,85.72 ; P5.20 93.68,84.46 ; P5.1 106.98,94.88 ; P5.1 105.72,94.88 ; P5.1 106.98,96.13 ; P5.1 105.72,96.13
  PWR_L6 w0.381: 107.01,15.81 107.01,16.63 ; 107.01,16.63 107.82,16.63 ; 107.01,16.63 106.19,16.63 ; 102.88,15.55 P15.7 ; P15.7 104.13,15.55 ; P15.7 104.13,14.3 ; P15.7 102.88,14.3 ; P15.16 103.5,18.94 ; P15.16 102.69,18.13 ; P15.16 104.32,18.13 ; 106.19,13.43 107.01,13.43 ; 107.01,13.43 107.01,12.61 ; 107.01,13.43 107.82,13.43 ; P13.4 90.67,13.43 ; P13.4 89.05,13.43 ; P13.4 89.86,12.61
  GND_L9 w0.381: P18.A2 114.92,45.44 ; P18.A2 114.92,43.09 ; P18.A2 116.6,44.26 ; P18.A2 113.25,44.26 ; P13.7 86.36,15.74 ; P13.7 85.55,14.92 ; P13.7 87.17,14.92 ; P1.SHLD1 48.13,93.42 ; P1.SHLD1 48.13,96.42 ; P1.SHLD1 46.32,93.42 ; P1.SHLD1 46.32,96.42 ; P3.6 57.87,69.3 ; P3.6 56.43,67.86 ; P3.6 56.43,69.3 ; P3.6 57.87,67.86 ; P15.16 104.32,18.13 ; P15.16 102.69,18.13 ; P15.16 103.5,18.94 ; 89.86,12.61 P13.4 ; P13.4 90.67,13.43 ; P13.4 89.05,13.43 ; P1.2 42.88,96.97 ; P1.2 39.67,96.97 ; P1.2 39.67,95.17 ; P1.2 42.88,95.17 ; 93.68,84.46 P5.20 ; P5.20 94.94,84.46 ; P5.20 94.94,85.72 ; P5.20 93.68,85.72 ; P6.11 81.28,97.2 ; P6.11 81.97,96.45 ; P6.11 81.28,95.7 ; 89.33,82.63 90.04,81.92 ; 90.04,81.92 89.33,81.2 ; 90.04,81.92 90.76,81.2 ; 90.04,81.92 90.76,82.63 ; P6.4 73.97,99.23 ; P6.4 74.85,98.35 ; P6.4 73.97,97.48 ; P6.4 73.09,98.35 ; 107.01,12.61 107.01,13.43 ; 107.01,13.43 106.19,13.43 ; 107.01,13.43 107.82,13.43 ; 25.1,45.72 P10.1 ; P10.1 26.04,46.66 ; P10.1 26.97,45.72 ; P10.1 26.04,44.78 ; 105.72,96.13 P5.1 ; P5.1 105.72,94.88 ; P5.1 106.98,96.13 ; P5.1 106.98,94.88 ; 17.14,43.09 17.14,44.26 ; 17.14,44.26 18.81,44.26 ; 17.14,44.26 15.46,44.26 ; 17.14,44.26 17.14,45.44 ; 53.04,2.25 S2.1 ; S2.1 53.98,3.19 ; S2.1 54.91,2.25 ; 78.56,16.84 MH5.1 ; MH5.1 81.97,20.25 ; MH5.1 78.56,20.25 ; MH5.1 81.97,16.84 ; 116.08,93.83 J4.3 ; J4.3 115.14,94.77 ; J4.3 117.02,94.77 ; J4.3 116.08,95.71 ; 107.01,16.63 107.82,16.63 ; 107.01,16.63 106.19,16.63 ; 107.01,16.63 107.01,15.81 ; 15.46,86.17 17.14,86.17 ; 17.14,86.17 17.14,85 ; 17.14,86.17 18.81,86.17 ; 17.14,86.17 17.14,87.35 ; P2.6 47.71,69.3 ; P2.6 47.71,67.86 ; P2.6 46.27,69.3 ; P2.6 46.27,67.86 ; P16.A2 114.92,87.35 ; P16.A2 114.92,85 ; P16.A2 116.6,86.17 ; P16.A2 113.25,86.17 ; 77.47,95.7 P6.8 77.47,97.2 ; J3.3 116.08,98.25 ; J3.3 117.02,97.31 ; J3.3 116.08,96.37 ; J3.3 115.14,97.31 ; 30.52,105.32 S1.1 ; S1.1 31.46,104.38 ; S1.1 32.4,105.32 ; 110.06,92.23 J6.1 ; J6.1 111,93.17 ; J6.1 111,91.29 ; J6.1 111.94,92.23 ; P15.7 104.13,15.55 ; P15.7 102.88,15.55 ; P15.7 104.13,14.3 ; P15.7 102.88,14.3 ; P1.SHLD4 36.23,101.62 ; P1.SHLD4 36.23,98.62 ; P1.SHLD4 34.42,101.62 ; P1.SHLD4 34.42,98.62 ; P1.SHLD2 36.23,93.42 ; P1.SHLD2 34.42,96.42 ; P1.SHLD2 34.42,93.42 ; P1.SHLD2 36.23,96.42 ; 73.66,95.7 P6.5 ; P6.5 73.66,97.2 ; P6.5 72.97,96.45 ; 46.32,98.62 P1.SHLD3 ; P1.SHLD3 48.13,101.62 ; P1.SHLD3 48.13,98.62 ; P1.SHLD3 46.32,101.62 ; 119.38,47.6 J1.2 ; J1.2 118.69,48.29 ; J1.2 120.07,48.29
  GND_L11 w0.381: P1.2 42.88,95.17 ; P1.2 39.67,95.17 ; P1.2 42.88,96.97 ; P1.2 39.67,96.97 ; 46.27,67.86 P2.6 ; P2.6 46.27,69.3 ; P2.6 47.71,67.86 ; P2.6 47.71,69.3 ; P6.11 81.97,96.45 ; P6.11 81.28,97.2 ; P6.11 81.28,95.7 ; 113.25,44.26 P18.A2 ; P18.A2 116.6,44.26 ; P18.A2 114.92,43.09 ; P18.A2 114.92,45.44 ; 34.42,96.42 P1.SHLD2 ; P1.SHLD2 34.42,93.42 ; P1.SHLD2 36.23,93.42 ; P1.SHLD2 36.23,96.42 ; 93.68,84.46 P5.20 ; P5.20 94.94,85.72 ; P5.20 94.94,84.46 ; P5.20 93.68,85.72 ; P13.7 87.17,14.92 ; P13.7 85.55,14.92 ; P13.7 86.36,15.74 ; 73.66,95.7 P6.5 ; P6.5 73.66,97.2 ; P6.5 72.97,96.45 ; 34.42,98.62 P1.SHLD4 ; P1.SHLD4 34.42,101.62 ; P1.SHLD4 36.23,98.62 ; P1.SHLD4 36.23,101.62 ; J3.3 117.02,97.31 ; J3.3 116.08,98.25 ; J3.3 116.08,96.37 ; J3.3 115.14,97.31 ; 31.46,104.38 S1.1 ; S1.1 30.52,105.32 ; S1.1 32.4,105.32 ; J4.3 116.08,95.71 ; J4.3 115.14,94.77 ; J4.3 117.02,94.77 ; J4.3 116.08,93.83 ; 107.01,12.61 107.01,13.43 ; 107.01,13.43 107.82,13.43 ; 107.01,13.43 106.19,13.43 ; 46.32,93.42 P1.SHLD1 ; P1.SHLD1 46.32,96.42 ; P1.SHLD1 48.13,96.42 ; P1.SHLD1 48.13,93.42 ; 17.14,86.17 18.81,86.17 ; 17.14,86.17 15.46,86.17 ; 17.14,86.17 17.14,87.35 ; 17.14,86.17 17.14,85 ; 111,91.29 J6.1 ; J6.1 111,93.17 ; J6.1 111.94,92.23 ; J6.1 110.06,92.23 ; 106.19,16.63 107.01,16.63 ; 107.01,16.63 107.01,15.81 ; 107.01,16.63 107.82,16.63 ; 56.43,69.3 P3.6 ; P3.6 56.43,67.86 ; P3.6 57.87,67.86 ; P3.6 57.87,69.3 ; 89.33,82.63 90.04,81.92 ; 90.04,81.92 90.76,82.63 ; 90.04,81.92 89.33,81.2 ; 90.04,81.92 90.76,81.2 ; 17.14,43.09 17.14,44.26 ; 17.14,44.26 17.14,45.44 ; 17.14,44.26 18.81,44.26 ; 17.14,44.26 15.46,44.26 ; P1.SHLD3 48.13,101.62 ; P1.SHLD3 46.32,98.62 ; P1.SHLD3 48.13,98.62 ; P1.SHLD3 46.32,101.62 ; P13.4 90.67,13.43 ; P13.4 89.86,12.61 ; P13.4 89.05,13.43 ; P5.1 106.98,96.13 ; P5.1 106.98,94.88 ; P5.1 105.72,96.13 ; P5.1 105.72,94.88 ; 114.92,85 P16.A2 ; P16.A2 116.6,86.17 ; P16.A2 113.25,86.17 ; P16.A2 114.92,87.35 ; P6.4 73.97,99.23 ; P6.4 73.09,98.35 ; P6.4 73.97,97.48 ; P6.4 74.85,98.35 ; 78.56,16.84 MH5.1 ; MH5.1 81.97,16.84 ; MH5.1 78.56,20.25 ; MH5.1 81.97,20.25 ; 118.69,48.29 J1.2 ; J1.2 119.38,47.6 ; J1.2 120.07,48.29 ; 102.88,14.3 P15.7 ; P15.7 102.88,15.55 ; P15.7 104.13,15.55 ; P15.7 104.13,14.3 ; P10.1 26.97,45.72 ; P10.1 26.04,44.78 ; P10.1 25.1,45.72 ; P10.1 26.04,46.66 ; 53.04,2.25 S2.1 ; S2.1 54.91,2.25 ; S2.1 53.98,3.19 ; 77.47,95.7 P6.8 77.47,97.2 ; 102.69,18.13 P15.16 ; P15.16 103.5,18.94 ; P15.16 104.32,18.13
  BOTTOM w0.127: 63.78,46.33 63.78,46.1 C498.2 ; C498.2 63.53,46.01 ; C498.2 63.79,45.92 63.79,45.69
  BOTTOM w0.203: C171.2 57.16,50.67 57.02,50.67 56.77,50.42 56.35,50.42 55.74,51.02 55.74,51.56 v2(56.19,52.01)
  BOTTOM w0.254: C77.2 63.79,39.6 v2(63.39,39.21) ; C483.2 v1(89.28,29.59) ; v2(58.59,32.01) 58.59,32.09 C178.2 ; v2(69.79,44.01) 69.39,43.61 C201.2 ; C339.2 44.67,36.49 v2(44.98,36.8) ; v1(78.61,66.8) 78.66,66.85 U34.4 ; v1(74.17,75.31) 74.17,75.18 74.42,74.93 75.79,74.93 ; v2(66.59,39.21) U11.N15 C203.2 ; v2(66.59,39.21) 66.19,38.8 C91.2 ; v2(66.59,39.21) 66.19,39.6 C88.1 ; C592.2 v1(100.33,87.81) ; C286.2 U23.G1 v2(43.38,60.01) ; v2(72.99,46.41) 73.39,46.81 C118.2 ; C154.2 66.27,37.12 v2(66.59,36.81) 66.9,36.49 C146.2 66.9,36.32 v2(66.59,36.01) 66.27,35.69 C128.2 ; 75.79,73.91 73.5,73.91 ; R277.2 38.86,17.65 38.58,17.93 v2(38.58,19.2) U25.M9 C279.2 ; C382.2 U25.F9 v2(44.18,19.2) ; P12.14 v1(65.91,12.96) ; v2(44.98,59.21) 44.67,58.89 C287.2 ; D28.3 v1(108.46,19.43) ; v2(40.98,36.8) 40.67,37.12 C337.2 ; C150.2 U11.T21 v2(61.79,42.41) ; 92.84,16.85 v1(92.84,16.26) ; v2(63.39,39.21) 63.79,38.8 ; v2(63.39,39.21) 63.07,39.52 C166.2 ; 63.79,38.8 C82.2 ; 63.79,38.8 v2(63.39,38.41) 63.79,38 C83.2 ; C492.2 97.34,33.33 97.16,33.15 96.9,33.15 96.72,32.96 C489.2 v1(96.14,32.77) ; C199.2 U11.N14 v2(68.19,39.21) ; C593.2 96.91,80.06 v1(96.9,80.06) ; v1(103.78,79.93) 103.35,80.37 C591.2 ; C320.2 40.67,42.09 v2(40.98,42.41) ; C569.2 85.76,63.15 v1(85.78,63.12) ; v1(89.53,60.12) 89.73,59.93 C564.2 ; v2(69.79,41.61) 69.39,42 C75.2 ; C79.2 67.07,44.41 C141.1 ; R417.2 67.56,34.67 ; C383.2 44.67,20.31 v2(44.98,20) 45.3,20.31 C384.2 ; C587.2 v1(97.33,90.22) ; v1(90.81,60.55) 91.08,60.28 C568.2 ; v2(62.59,47.21) 62.9,46.89 C172.2 ; C132.2 72.59,34.8 v2(72.99,34.41) ; v2(64.99,44.01) 65.39,44.41 C182.2 ; v2(56.19,44.81) U11.W28 C160.2 ; 75.79,72.9 73.5,72.9 ; v2(66.59,41.61) 66.66,41.53 C105.2 ; v2(66.59,41.61) 66.19,42.01 C66.1 ; v2(66.59,41.61) 66.19,41.21 C198.2 ; v2(45.78,26.4) U25.D1 C368.2 ; v2(61.79,43.21) 62.1,42.89 C193.2 ; v2(48.18,52.81) U23.A9 C305.2 ; v2(48.18,41.61) U24.A9 C326.2 ; C276.2 U24.M9 v2(38.58,41.61) 38.58,40.67 39.19,40.06 R275.2 ; C161.2 58.99,46.81 v2(58.59,47.21) ; v2(40.98,53.61) 40.67,53.29 C294.2 ; C57.2 68.59,38.8 v2(68.19,39.21) ; C114.2 78.19,33.2 v2(78.59,33.61) ; C140.2 72.59,46 v2(72.19,46.41) ; C421.2 74.55,76.96 v1(74.17,77.34) ; C537.1 107.26,69.49 ; v2(60.19,29.61) 59.79,30.01 C138.2 ; v5(101.73,27.18) 101.49,26.94 U29.1 ; v2(44.18,30.4) U26.F9 C355.2 ; C280.2 41.3,25.29 v2(40.98,25.6) 40.67,25.92 C365.2 ; C68.2 64.59,43.61 v2(64.99,43.21) ; v2(70.59,47.21) U11.AB11 C243.2 ; C52.1 68.67,37.92 v2(68.99,37.61) ; C493.2 97.03,27.62 97.03,27.75 C487.2 v1(96.14,28.07) ; v2(71.39,31.21) 70.99,31.6 C135.2 ; v2(43.38,31.2) 43.07,31.52 C354.2 ; U30.1 101.49,32.02 v5(101.73,32.26) ; v1(63.86,13.23) 63.87,13.22 P12.10 ; D40.3 v1(86.61,5.97) ; C375.2 47.78,25.2 v2(47.38,24.8) ; v2(47.38,47.21) 47.78,47.61 C317.1 ; v1(74.17,71.37) 74.17,71.63 74.42,71.88 75.79,71.88 ; C381.2 43.07,20.31 v2(43.38,20) ; v5(79.49,85.59) 79.93,85.15 C470.2 ; C141.1 U11.W15 v2(66.59,44.01) ; C141.1 66.9,44.49 v2(66.59,44.81) ; C539.1 106.27,69.52 ; v2(45.78,37.6) U26.D1 C340.2 ; C535.1 88.99,69.23 ; C324.2 45.3,42.72 v2(44.98,42.41) 44.67,42.72 C323.2 ; C538.1 105.77,69.49 ; v2(47.38,58.41) 47.78,58.81 C291.2 ; C490.2 88.39,32.32 88.39,32.33 C482.2 v1(89.28,32.64) 89.28,32.89 88.99,33.18 C246.2 ; C168.2 56.59,36.4 v2(56.19,36.01) ; C301.2 U23.F9 v2(44.18,52.81) ; C115.2 74.19,34.8 v2(73.79,34.41) ; C173.2 62.9,46.09 v2(62.59,46.41) ; C123.2 70.99,42 v2(70.59,42.41) ; v2(40.98,59.21) 40.67,59.52 C285.2 ; C543.1 103.28,69.44 ; v2(68.19,39.21) 68.59,39.6 C200.2 ; v2(68.19,39.21) 67.79,38.8 C86.2 ; U16.6 102.98,39.1 v5(102.74,38.86) ; C386.2 U25.A9 v2(48.18,19.2) ; v2(45.78,42.41) 46.1,42.72 C325.2 ; C152.2 68.59,46 v2(68.19,46.41) U11.AA14 C144.2 ; C62.1 64.5,42.09 v2(64.19,42.41) ; v2(68.19,37.61) 67.79,38 C85.2 ; R274.2 R334.2 v1(53.47,41.15) ; C288.2 U23.D1 v2(45.78,60.01) ; C309.2 U24.G1 v2(43.38,48.81) ; v2(66.59,42.41) 66.19,42.81 C56.1 ; v2(69.79,35.21) 69.39,35.6 C58.1 ; v2(74.59,49.61) 74.27,49.92 C116.2 ; P12.13 v1(74.75,12.96) ; C349.2 40.67,30.89 v2(40.98,31.2) ; C471.2 77.55,84.52 v5(77.99,84.09) ; C120.2 76.59,42.01 v2(76.99,42.41) ; C322.2 U24.F9 v2(44.18,41.61) ; C540.1 104.24,69.44 ; C158.2 62.9,51.52 v2(62.59,51.21) 62.27,51.52 C184.2 ; C145.1 C142.2 U11.R21 v2(61.79,41.61) ; C165.2 58.99,42.01 v2(58.59,42.41) 58.99,42.81 C174.2 ; v2(43.38,26.4) U25.G1 C366.2 ; C275.2 U23.M9 v2(38.58,52.81) ; v2(66.59,43.21) U11.V15 C76.2 ; C534.1 91,69.17 ; C304.2 46.1,53.92 v2(45.78,53.61) ; v2(47.38,26.4) U25.B1 C374.2 ; C499.2 66.19,46.01 v2(66.59,46.41) 66.19,46.81 C95.1 ; v2(59.39,48.81) 58.99,48.41 C159.2 ; v1(106.02,87.58) 106.32,87.28 C590.2 ; v2(68.99,41.61) U11.R13 C72.1 ; v1(94.61,28.07) 94.3,27.75 C486.2 ; C338.2 U26.G1 v2(43.38,37.6) ; C359.2 46.1,31.52 v2(45.78,31.2) ; C127.2 70.1,36.32 v2(69.79,36.01) 69.39,36.4 C61.2 ; v2(44.98,25.6) 44.67,25.29 C367.2 ; C60.1 70.19,42 v2(69.79,42.41) ; C300.2 43.07,53.92 v2(43.38,53.61) ; C69.2 U11.U20 v2(62.59,43.21) ; C485.2 v1(92.46,26.42) ; C360.2 U26.A9 v2(48.18,30.4) ; C357.2 45.3,31.52 v2(44.98,31.2) 44.67,31.52 C356.2 ; C588.2 v1(100.33,98.17) ; v2(43.38,42.41) 43.07,42.72 C321.2 ; C303.2 45.3,53.92 v2(44.98,53.61) 44.67,53.92 C302.2 ; C532.1 92.52,69.23 ; v2(40.98,20) 40.67,19.69 C378.2 ; C164.2 60.67,46.09 v2(60.99,46.41) 60.67,46.72 C162.2 60.67,46.89 v2(60.99,47.21) 60.67,47.52 C170.2 ; v2(47.38,48.81) U24.B1 C316.2 ; 94.49,16.85 v1(94.49,16.26) ; C236.2 U11.AA11 v2(70.59,46.41) ; C308.2 40.67,48.32 v2(40.98,48.01) ; C119.2 76.59,44.41 v2(76.99,44.81) ; C266.2 91.5,43.24 v2(91.31,43.05) ; v2(73.79,33.61) 74.19,33.2 C134.2 ; C488.2 v1(96.14,31.62) ; C346.2 47.78,36.4 v2(47.38,36) 46.67,36 C344.2 ; v2(76.99,39.21) 76.59,39.6 C121.2 ; C484.2 v1(90.93,26.42) ; v2(47.38,37.6) U26.B1 C345.2 ; v2(44.98,48.01) 44.67,47.69 C310.2 ; C586.2 v1(94.31,98.17) ; v1(90.68,28.07) 90.99,27.75 C491.2 ; C290.1 U23.B1 v2(47.38,60.01) ; C536.1 89.5,69.23 ; C544.1 107.77,69.52 ; C541.1 104.75,69.47 ; C530.1 93.51,69.18 ; C533.1 90.49,69.2 ; v2(71.39,42.41) 71.07,42.72 C67.1 ; C589.2 v1(103.35,90.22) ; C136.2 66.19,31.6 v2(65.79,31.21) ; C157.2 56.58,51.61 v2(56.19,52.01) ; C531.1 92.02,69.26 ; R422.2 v2(68.99,48.81) ; v2(45.78,48.81) U24.D1 C311.2 ; D32.3 v1(77.47,99.57) ; C385.2 46.1,20.31 v2(45.78,20) ; v2(74.59,29.61) 74.19,30 C133.2 ; C529.1 94.02,69.22 ; C563.2 85.76,64.69 v1(85.8,64.64) ; C542.1 102.77,69.44
  BOTTOM w0.381: v5(29.08,20.19) 30.1,20.19 30.1,18.67 29.97,18.54 v1(28.58,18.54) ; v1(99.38,63.41) 99.35,63.45 C576.2 ; P16.1 v1(119.13,81.45) ; R278.2 39.09,28.86 v1(38.6,29.35) ; v1(111.51,42.71) 110.33,41.53 C445.2 ; 90.16,59.53 C564.2 90.59,59.93 ; P16.60 115.91,58.25 v1(116.2,58.55) ; R384.2 24,104.68 v1(24,104.14) v1(24.51,104.14) 24.51,104.68 R384.2 ; R384.2 R332.1 ; v1(122.3,60.45) 122.3,60.07 122.08,59.85 P16.28 ; U32.7 109.35,49.53 ; 109.35,49.53 v1(109.35,50.42) 108.97,50.8 U32.8 ; 109.35,49.53 109.35,48.26 ; C474.1 v1(21.46,97.28) ; v1(85.09,27.81) 85.6,27.81 85.89,27.53 C235.2 ; C233.1 98.71,70.02 ; C233.1 C232.1 ; C233.1 98.31,69.6 ; C579.2 v1(103.76,73.61) ; C579.2 104.19,73.02 ; C579.2 103.33,73.02 ; C64.2 C70.2 C80.2 81.12,34.58 C122.2 v1(82.3,34.29) ; C64.2 v1(81.79,37.59) ; C64.2 C63.2 ; P16.31 v1(115.82,81.45) ; R276.2 v1(40.19,51.26) ; C81.2 56.13,77.85 56.39,77.6 v1(56.39,77.47) ; v1(44.7,64.14) 44.32,64.52 C10.2 ; P4.16 v1(74.3,17.02) ; D34.2 110.9,20.82 v1(110.87,20.79) R300.1 ; R43.2 R205.2 v1(57.66,26.92) C113.2 ; C387.2 47.75,29.97 v2(48.18,30.4) ; P19.1 v1(21.34,81.45) ; U8.3 51.31,81.92 ; 51.31,81.92 51.31,82.8 50.93,83.19 U8.4 49.53,83.19 49.15,83.57 v1(49.15,84.19) ; 51.31,81.92 51.31,80.64 ; C230.1 53.46,2.76 S2.1 ; R58.2 C111.2 51.62,65.39 51.61,65.38 v1(51.61,64.64) ; 84.36,68.35 C217.1 ; C217.1 84.77,67.92 ; C217.1 C218.1 ; Y8.1 28.54,44.86 ; Y8.1 29.29,43.98 ; Y8.1 28.54,43.11 ; Y8.1 27.79,43.98 ; R397.2 116.08,47.88 v1(116.46,47.5) 115.95,46.99 C443.2 ; P12.12 v1(76.61,2.48) ; C63.2 81.12,39.59 C53.2 v1(82.3,39.88) ; C63.2 v1(81.79,38.61) ; R386.1 v1(91.19,3.56) ; v2(65.39,74.41) 65.43,74.46 R319.1 ; C265.2 61.69,95.12 61.31,94.74 v1(60.07,94.74) ; C265.2 C264.2 ; C265.2 v1(62.36,95.5) ; P19.34 18.12,79.05 v1(18.92,79.85) ; C218.1 84.77,69.57 ; C218.1 84.36,69.14 ; v2(45.78,37.6) 46.22,38.04 C341.2 ; R478.1 101.77,65.79 ; R478.1 101.35,65.39 ; R478.1 100.92,65.79 ; R416.2 87.76,83.19 89.03,81.92 90.04,81.92 ; P19.41 v1(18.03,73.45) ; P18.31 v1(115.82,39.54) ; 91.09,72.74 C566.2 ; C566.2 91.94,72.74 ; C566.2 v1(91.52,73.33) ; FB9.1 v1(59.31,21.08) ; v1(30.23,36.07) 30.51,36.36 C263.1 ; P17.1 v1(21.34,39.54) ; v1(59.05,70.36) C46.2 C48.2 v1(59.05,71.37) ; 30.1,23.24 v1(28.58,23.24) ; 30.1,23.24 30.1,24.77 ; 30.1,23.24 30.1,21.72 v5(29.08,21.72) v5(28.07,21.72) ; U8.1 50.93,79.38 51.31,79.76 51.31,80.64 ; v1(59.05,73.41) R22.2 C43.2 ; 70.48,18.88 v1(70.48,20.83) ; v1(71.86,4.62) 72.44,4.04 72.44,3.28 72.02,2.85 P12.6 ; U42.1 102.12,9.16 101.85,8.89 101.85,8.13 102.12,7.86 U42.3 ; P18.2 118.62,38.74 118.24,39.12 v1(118.24,39.54) ; C216.1 31.84,104.94 S1.1 ; v1(71.12,64.77) C92.1 C33.2 v1(70.1,64.77) ; v1(73.15,61.98) 73.53,61.59 C110.2 ; v1(53.47,31.62) v1(52.7,31.62) 52.7,30.86 C180.2 53.47,30.86 v1(53.47,31.62) ; v1(53.47,31.62) 53.47,32.13 53.72,32.38 C179.2 ; C572.2 99.35,65.93 ; C572.2 98.94,65.51 ; C572.2 99.35,64.95 v1(99.38,64.91) ; v1(74.17,69.34) C17.1 R421.2 ; U42.3 v1(103.62,7.86) ; U42.3 102.81,6.5 Q7.2 ; 98.94,64.03 C576.2 ; C576.2 99.35,64.46 ; C245.2 81.12,49.24 C130.2 v1(81.41,50.42) ; C245.2 v1(81.79,48.26) ; C245.2 C237.2 81.12,46.26 C238.2 ; C429.2 v1(28.45,49.53) ; C430.2 v1(32,53.34) ; v1(53.47,44.83) 53.47,45.59 C156.2 52.7,45.59 v1(52.7,44.83) v1(53.47,44.83) ; v1(53.47,44.83) 53.47,44.45 53.72,44.2 C163.2 ; v1(74.17,75.31) 74.04,75.44 C26.1 C29.1 C21.1 C22.1 C25.1 v1(74.17,71.37) ; 98.31,68.68 C232.1 ; C232.1 98.71,68.25 ; v2(48.18,52.81) 47.75,52.37 C312.2 ; C452.2 76.84,79.12 v1(76.96,78.99) 76.75,78.78 Y9.4 ; v1(112.65,60.07) 112.87,59.85 P16.58 ; Y8.4 30.89,43.98 ; Y8.4 30.14,43.11 ; Y8.4 30.14,44.86 ; Y8.4 29.39,43.98 ; P19.50 v1(18.03,66.25) ; P17.31 v1(18.03,39.54) ; 68.77,49.04 R422.2 69.41,49.24 ; C478.2 v1(28.7,104.27) ; P19.29 v1(21.34,59.05) ; C479.2 v1(92.71,3.94) ; R28.1 R26.2 C35.2 C37.2 ; P19.54 v1(18.03,63.05) ; v1(116.71,39.54) 116.71,39.12 116.33,38.74 P18.32 ; v1(60.2,62.61) 59.82,62.61 59.56,62.36 C189.2 ; P19.51 v1(18.03,65.45) ; v1(92.71,28.07) 93.6,28.07 93.85,28.32 C481.2 93.85,29.59 93.6,29.84 v1(92.71,29.84) 91.82,29.84 91.57,30.1 C494.2 91.57,31.37 91.82,31.62 v1(92.71,31.62) ; v1(72.64,58.17) C497.2 72.9,56.77 73.28,56.77 73.79,56.26 L24.2 L11.2 77.22,56.26 77.72,56.77 78.11,56.77 C202.2 v1(78.36,58.17) ; v2(45.78,48.81) 46.22,49.24 C327.2 ; C361.2 47.75,18.76 v2(48.18,19.2) ; C580.2 v1(106.76,73.63) ; C580.2 107.18,73.04 ; C580.2 106.33,73.04 ; P16.30 v1(119.13,58.25) ; U8.2 51.31,80.64 ; C19.1 C16.1 ; v1(107.82,39.12) R200.1 R203.2 ; C257.2 54.23,21.08 v1(55.12,21.08) ; C473.1 v1(115.44,4.32) ; 97.91,65.15 C567.2 97.5,65.58 ; 27.79,46.19 Y8.2 28.54,45.31 ; P19.60 v1(18.03,58.25) ; 73.75,80.98 73.75,80.9 73.37,80.52 72.9,80.52 72.46,80.08 v1(72.46,79.91) 72.26,79.72 72.26,79.44 C453.2 ; C45.2 69,79.21 69.36,79.57 R323.1 ; C45.2 C39.2 v1(67.69,79.88) ; C45.2 v1(68.71,79.88) ; C500.1 C37.2 ; C500.1 C24.1 v1(62.99,64.77) ; C500.1 v1(64.01,64.77) ; C37.2 v1(65.02,64.77) ; C441.1 v1(51.82,104.14) ; v1(111.02,65) 111.04,65.02 ; 91.87,60.28 C568.2 91.44,59.88 ; C407.2 C405.2 107.15,26.7 v1(107.19,26.67) ; C238.2 v1(82.3,45.97) ; C238.2 C54.2 v1(82.3,44.45) ; C41.2 v1(64.64,79.88) ; C496.2 70.14,76.05 v2(70.19,76.01) ; v1(27.32,36.08) 27.59,36.36 R236.2 ; P19.9 v1(24.38,75.05) ; v1(18.92,81.45) 18.92,81.03 18.54,80.65 P19.32 ; P19.13 v1(21.34,71.85) ; 92.59,72.74 C571.2 ; C571.2 v1(93.01,73.33) ; C571.2 93.44,72.74 ; R403.1 v1(121.67,88.77) ; U10.3 v1(80.66,63.37) ; C570.2 90.45,72.74 ; C570.2 89.59,72.74 ; C570.2 v1(90.02,73.33) ; R400.1 v1(21.72,3.3) ; R69.1 v1(96.72,99.47) ; P19.5 21.59,78.25 21.34,78.5 v1(21.34,79.05) P19.4 ; U32.6 109.35,48.26 ; 109.35,48.26 109.35,47.37 108.97,46.99 U32.5 ; C258.2 C259.2 55.21,17.11 v1(55.12,17.02) ; 85.37,64.85 C563.2 85.36,65.28 ; C27.1 C28.1 C20.1 C16.1 ; C94.2 v1(78.61,59.31) ; 111.44,66.4 C575.2 111.04,66.82 ; C268.2 v1(93.34,50.42) ; R12.2 v1(36.23,80.87) ; C432.2 v1(29.46,50.8) ; 111.04,65.21 C573.2 111.44,65.63 ; R411.2 67.47,72.33 v2(67.79,72.01) ; C431.2 31.24,56.64 v1(30.99,56.39) 30.48,55.88 L22.2 ; C574.2 103.58,60.21 v1(103.36,60.42) ; C574.2 104.39,60.21 ; C574.2 103.96,59.8 ; C231.1 v1(81.53,3.56) ; v1(54.08,67.84) C112.2 ; 85.76,64.16 C569.2 85.36,63.73 ; P19.31 v1(18.03,81.45) ; P19.38 v1(18.03,75.85) ; R97.2 v1(100.05,78.69) ; D37.2 v1(82.93,103) ; P4.12 v1(71.75,17.02) ; R385.1 61.47,2.76 v1(61.59,2.63) ; D36.2 101.34,20.95 v1(101.85,21.46) ; v1(61.72,21.08) 62.61,21.08 C254.2 ; C215.1 v1(112.93,100.05) ; P16.32 116.33,80.65 116.71,81.03 v1(116.71,81.45) ; D42.2 v1(89.29,6.1) ; P19.26 v1(21.21,61.45) ; v1(107.19,34.29) 107.15,34.26 C414.2 C412.2 ; v1(91.12,33.4) 91.28,33.56 R209.1 R328.2 R207.1 ; v1(56.01,8.89) 56.01,9.51 56.28,9.78 C109.2 ; C267.1 90.74,43.43 91.12,43.05 v2(91.31,43.05) ; R47.2 v1(59.44,26.92) ; P4.20 v1(76.84,17.02) ; R299.1 v1(84.58,104.14) ; R404.2 76.49,68.36 v1(76.45,68.33) R24.2 R27.2 v1(76.45,69.34) ; C270.1 v1(97.94,41.27) ; v1(85.09,6.1) 85.06,6.07 P7.5 ; C435.2 v1(30.95,47.5) ; P4.8 v1(69.22,17.02) ; C472.1 v1(21.72,4.32) ; P19.47 v1(18.03,68.65) ; R401.1 v1(115.44,3.3) ; C197.2 v1(60.71,54.74) ; C197.2 R333.2 59.4,54.07 59.25,53.91 59.25,53.63 59.13,53.52 58.81,53.52 C190.2 ; C197.2 60.76,54.01 L10.2 62.29,54.07 R50.2 R49.2 C99.2 ; C350.2 46.22,26.84 v2(45.78,26.4) ; R331.1 v1(100.38,100.13) ; v1(118.24,81.45) 118.24,81.03 118.62,80.65 P16.2 ; P19.23 v1(21.34,63.85) 21.34,64.39 21.6,64.65 P19.22 ; C16.1 v1(76.45,72.39) ; C577.2 104.77,60.66 v1(104.58,60.85) ; C577.2 105.63,60.66 ; C577.2 105.21,60.26 ; v1(59.31,14.48) 59.22,14.57 C262.2 ; R410.2 v1(99.31,5.08) 99.31,4.06 99.09,3.84 C495.2 ; P4.4 v1(66.68,17.02) ; R387.1 v1(63.75,104.14) ; v1(61.72,18.41) 61.69,18.45 C253.2 ; P17.2 20.83,38.74 20.45,39.12 v1(20.45,39.54) ; 97.5,63.96 C565.2 97.91,64.39 ; v1(18.92,39.54) 18.92,39.12 18.54,38.74 P17.32 ; C578.2 105.69,73.04 ; C578.2 v1(105.26,73.63) ; C578.2 104.83,73.04 ; v2(48.18,41.61) 47.75,41.17 C369.2 ; C240.2 v1(87.5,20.07) ; P19.44 v1(18.03,71.05) ; v1(76.84,63.37) 77.22,63.37 77.47,63.12 U9.2 ; C415.1 v1(70.36,104.14) ; P19.37 v1(18.03,76.65) ; v1(97.51,65.76) 97.5,65.75 ; C131.2 v1(82.3,41.66) ; P19.19 v1(21.34,67.05) ; C419.2 v1(79.76,15.37) ; R434.2 41.94,69.22 v5(42.67,69.22) ; C389.2 v5(28.07,20.19) ; C434.2 v1(26.83,47.5) ; C269.2 v1(92.46,50.42) ; R402.1 v1(21.46,96.27) ; P12.11 v1(62.66,2.26) ; R98.1 v1(91.57,78.74) ; v1(111.05,67.01) 111.04,67 ; P19.16 v1(21.34,69.45) ; P19.10 v1(21.34,74.25) ; C475.1 v1(120.65,88.77) ; C428.2 v1(28.45,52.07) ; P18.1 v1(119.13,39.54) ; C97.2 v1(81.41,59.31) ; C23.2 v1(59.05,69.09) ; R21.2 v1(59.05,75.44) ; 84.05,68.35 v1(84.02,68.33) ; D35.2 v1(82.8,10.03) ; R68.2 v1(103.86,99.54) ; C18.1 v1(74.17,70.36) ; P19.57 v1(18.03,60.65) ; v1(74.17,64.77) v1(74.17,65.53) 73.41,65.53 73.03,65.15 73.41,64.77 v1(74.17,64.77)
  vias: v1(26.8,76.33) v1(27.81,76.33) v1(28.83,80.39) v1(28.83,79.25) v1(28.83,78.11) v1(28.83,76.33) v1(28.96,86.61) v1(28.96,72.64) v1(29.46,52.07) v1(29.46,49.53) v1(29.72,86.61) v1(29.72,72.64) v1(29.84,80.39) v1(29.84,79.25) v1(29.84,78.11) v1(29.84,76.33) v1(30.48,86.61) v1(30.48,72.64) v1(30.48,52.07) v1(30.48,50.8) v1(30.86,76.33) v1(30.99,66.55) v1(30.99,65.41) v1(30.99,64.26) v1(31.24,86.61) v1(31.24,72.64) v1(31.75,66.55) v1(31.75,65.41) v1(31.75,64.26) v1(31.88,76.33) v1(32,86.61) v1(32,72.64) v1(32.51,66.55) v1(32.51,65.41) v1(32.51,64.26) v1(36.13,76.1) v1(49.78,90.17) v1(52.07,90.17) v1(54.61,90.17) v1(55.37,63.88) v1(55.37,63.25) v1(55.37,62.61) v1(56.62,67.34) v1(57.15,90.17) v1(57.28,67.34) v1(59.44,90.17) v1(60.2,63.88) v1(60.2,63.25) v1(63.22,82.8) v1(63.22,82.17) v1(63.22,81.53) v1(65.02,63.88) v1(65.02,63.25) v1(65.02,62.61) v1(66.6,83.44) v1(66.6,82.8) v1(66.6,82.17) v1(66.6,81.53) v1(68.22,9.22) v1(69.67,12.95) v1(69.9,82.78) v1(69.9,82.14) v1(69.9,81.51) v1(70.74,88.27) v1(71.55,10.79) v1(72.52,88.27) v1(73.15,63.25) v1(73.15,62.61) v1(73.91,85.45) v1(73.94,83.95) v1(73.94,83.26) v1(73.94,82.55) v1(74.3,88.27) v1(76.45,101.6) v1(76.96,87.38) v1(78.49,101.6) v1(78.49,2.01) v1(80.52,87.38) v1(84.02,69.14) v1(84.99,32.38) v1(84.99,31.75) v1(86.33,32.38) v1(86.33,31.75) v1(86.51,34.29) v1(89.22,68.53) v1(89.22,67.51) v1(89.22,66.49) v1(89.22,65.48) v1(89.22,64.46) v1(90.24,68.53) v1(90.24,67.51) v1(90.24,66.49) v1(90.24,65.48) v1(90.24,64.46) v1(90.81,31.62) v1(90.81,29.84) v1(91.25,68.53) v1(91.25,67.51) v1(91.25,66.49) v1(91.25,65.48) v1(91.25,64.46) v1(92.27,68.53) v1(92.27,67.51) v1(92.27,66.49) v1(92.27,65.48) v1(92.27,64.46) v1(93.29,68.53) v1(93.29,67.51) v1(93.29,66.49) v1(93.29,65.48) v1(93.29,64.46) v1(94.61,31.62) v1(94.61,29.84) v1(96.77,24.64) v1(98.12,69.6) v1(98.09,68.68) v1(98.42,29.84) v1(100.84,40.39) v1(101.31,49.44) v1(101.6,40.39) v1(101.75,49.81) v1(101.88,50.37) v1(102.43,50.51) v1(102.36,44.32) v1(102.36,43.18) v1(102.36,42.04) v1(102.36,40.39) v1(102.91,50.24) v1(102.97,68.82) v1(102.97,67.8) v1(102.97,66.79) v1(102.97,65.77) v1(102.97,64.75) v1(103.38,44.32) v1(103.38,43.18) v1(103.38,42.04) v1(103.38,40.39) v1(103.99,68.82) v1(103.99,67.8) v1(103.99,66.79) v1(103.99,65.77) v1(103.99,64.75) v1(104.14,40.39) v1(104.9,40.39) v1(105,68.82) v1(105,67.8) v1(105,66.79) v1(105,65.77) v1(105,64.75) v1(106.02,68.82) v1(106.02,67.8) v1(106.02,66.79) v1(106.02,65.77) v1(106.02,64.75) v1(107.04,68.82) v1(107.04,67.8) v1(107.04,66.79) v1(107.04,65.77) v1(107.04,64.75) v1(109.98,34.29) v1(109.98,30.48) v1(109.98,26.67) v1(110.87,34.29) v1(110.87,30.48) v1(110.87,26.67) v5(43.69,69.22) v5(79.49,84.09) v5(101.73,38.86) v5(101.73,37.34) v5(102.23,38.1) v5(102.23,33.02) v5(102.23,27.94) v5(102.74,37.34) v5(102.74,33.78) v5(102.74,32.26) v5(102.74,28.7) v5(102.74,27.18)
